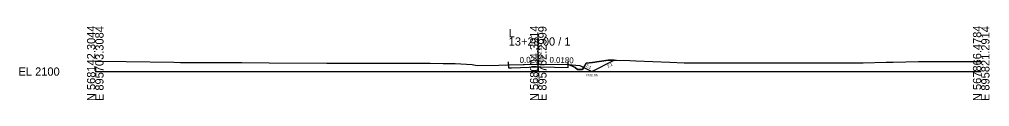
# Model space of a CAD drawing. Extents: x -26 to 1603, y -10 to 13527.
# Drawn here: x -25.7 to 302.8, y 490.3 to 515.5 of the extents above; entities that cross this region are included whole.
import ezdxf

# ---------------------------------------------------------------- set-up
doc = ezdxf.new("R2010")
doc.units = 0
for name, color, linetype in [('Default', 7, 'Continuous'), ('Exist XS Center Line Elevation Label', 7, 'Continuous'), ('Exist XS Ground Line', 7, 'Continuous'), ('Old_Level_61', 7, 'Continuous'), ('Old_Level_63', 7, 'Continuous'), ('Prop XS Ditch Standard Text', 7, 'Continuous'), ('Prop XS Earthwork Shape', 7, 'Continuous'), ('Prop XS EOT Tick Mark', 7, 'Continuous'), ('Prop XS Finish Grade Earthwork', 7, 'Continuous'), ('Prop XS Finish Grade Pavement', 7, 'Continuous'), ('Prop XS Side Slope Text', 7, 'Continuous'), ('Prop XSC Text', 7, 'Continuous')]:
    doc.layers.add(name, color=color, linetype=linetype)

msp = doc.modelspace()

# ---------------------------------------------------------------- linework, layer by layer
at = {"layer": 'Exist XS Ground Line'}
for p, q in [((0, 503.58), (1.9, 503.55)), ((1.9, 503.55), (10.48, 503.42)), ((10.48, 503.42), (26.61, 503.13)), ((26.61, 503.13), (28.82, 503.12)), ((28.82, 503.12), (30.49, 503.09)), ((30.49, 503.09), (44.55, 503.09)), ((44.55, 503.09), (47.96, 503.08)), ((47.96, 503.08), (48.78, 503.04)), ((48.78, 503.04), (49.64, 503.03)), ((49.64, 503.03), (58.91, 502.97)), ((58.91, 502.97), (78.41, 502.89)), ((78.41, 502.89), (84.58, 502.84)), ((84.58, 502.84), (95.98, 502.82)), ((95.98, 502.82), (100.76, 502.79)), ((100.76, 502.79), (109.26, 502.9)), ((109.26, 502.9), (113.38, 502.79)), ((113.38, 502.79), (117.78, 502.75)), ((117.78, 502.75), (120.43, 502.7)), ((120.43, 502.7), (121.91, 502.68)), ((121.91, 502.68), (127.65, 502.34)), ((165.71, 501.83), (166.24, 502.8)), ((166.24, 502.8), (168.33, 503.07)), ((168.33, 503.07), (173.66, 503.86)), ((173.66, 503.86), (176.48, 503.84)), ((176.48, 503.84), (181.01, 503.74)), ((181.01, 503.74), (183.04, 503.65)), ((183.04, 503.65), (188.8, 503.4)), ((188.8, 503.4), (194.55, 503.13)), ((194.55, 503.13), (199.43, 503.01)), ((199.43, 503.01), (200.39, 502.99)), ((200.39, 502.99), (210.5, 502.92)), ((210.5, 502.92), (216.99, 502.96)), ((216.99, 502.96), (223.29, 502.96)), ((223.29, 502.96), (236.58, 502.97)), ((236.58, 502.97), (249.73, 502.91)), ((249.73, 502.91), (253.16, 502.95)), ((253.16, 502.95), (256.79, 502.95)), ((256.79, 502.95), (259.99, 503.01)), ((259.99, 503.01), (267.82, 503.16)), ((267.82, 503.16), (268.75, 503.19)), ((268.75, 503.19), (270.19, 503.21)), ((270.19, 503.21), (278.78, 503.36)), ((278.78, 503.36), (280.93, 503.4)), ((280.93, 503.4), (289.92, 503.42)), ((289.92, 503.42), (296.56, 503.39)), ((296.56, 503.39), (300, 503.41)), ((127.65, 502.34), (129.32, 502.02)), ((129.32, 502.02), (136.66, 502.21)), ((136.66, 502.21), (139.87, 502.26)), ((139.87, 502.26), (150.03, 502.55)), ((150.03, 502.55), (150.49, 502.56)), ((150.49, 502.56), (150.88, 502.56)), ((150.88, 502.56), (160.11, 502.39)), ((160.11, 502.39), (161.38, 501.98)), ((161.38, 501.98), (162.54, 501.38)), ((162.54, 501.38), (163.34, 500.73)), ((163.34, 500.73), (163.9, 500.73)), ((163.9, 500.73), (164.97, 500.73)), ((164.97, 500.73), (165.71, 501.83))]:
    msp.add_line(p, q, dxfattribs=at)
at = {"layer": 'Old_Level_61'}
for p, q in [((139.9, 502.26), (139.9, 501.26)), ((139.9, 501.26), (140.9, 501.29)), ((140.9, 501.29), (150.03, 501.55)), ((150.03, 501.55), (150.49, 501.56)), ((150.49, 501.56), (150.88, 501.56)), ((150.88, 501.56), (160.11, 501.39)), ((160.11, 501.39), (160.13, 501.38)), ((160.13, 501.38), (160.13, 502.38))]:
    msp.add_line(p, q, dxfattribs=at)
at = {"layer": 'Old_Level_63'}
for p, q in [((150, 500), (150, 511.59)), ((0, 500), (150, 500)), ((150, 500), (300, 500))]:
    msp.add_line(p, q, dxfattribs=at)
at = {"layer": 'Prop XS Earthwork Shape'}
for points in [[(168.15, 500.05), (175.75, 503.85), (173.66, 503.86), (168.33, 503.07), (166.24, 502.8), (165.71, 501.83), (165.43, 501.41)], [(168.15, 500.05), (175.75, 503.85), (173.66, 503.86), (168.33, 503.07), (166.24, 502.8), (165.71, 501.83), (165.43, 501.41)], [(160.11, 502.39), (164.11, 502.07), (165.43, 501.41), (164.97, 500.73), (163.9, 500.73), (163.34, 500.73), (162.54, 501.38), (161.38, 501.98)], [(160.11, 502.39), (164.11, 502.07), (165.43, 501.41), (164.97, 500.73), (163.9, 500.73), (163.34, 500.73), (162.54, 501.38), (161.38, 501.98)]]:
    msp.add_lwpolyline(points, close=True, dxfattribs=at)
at = {"layer": 'Prop XS EOT Tick Mark'}
for p, q in [((139.9, 502.26), (139.9, 503.26)), ((160.11, 502.39), (160.11, 503.39))]:
    msp.add_line(p, q, dxfattribs=at)
at = {"layer": 'Prop XS Finish Grade Earthwork'}
for p, q in [((168.15, 500.05), (175.75, 503.85)), ((160.11, 502.39), (164.11, 502.07)), ((164.11, 502.07), (168.15, 500.05))]:
    msp.add_line(p, q, dxfattribs=at)
at = {"layer": 'Prop XS Finish Grade Pavement'}
for p, q in [((139.9, 502.26), (150.5, 502.56)), ((150.5, 502.56), (160.11, 502.39))]:
    msp.add_line(p, q, dxfattribs=at)

# ---------------------------------------------------------------- texts
at = {"layer": 'Default'}
for s, rotation, p in [('0.0280', 1.1458, (143.71, 502.92)), ('0.0180', 358.8542, (153.79, 502.97))]:
    msp.add_text(s, height=2, rotation=rotation, dxfattribs=at).set_placement(p)
at = {"layer": 'Exist XS Center Line Elevation Label'}
msp.add_text('2102.55', height=1, rotation=90, dxfattribs=at).set_placement((150.5, 495.02))
at = {"layer": 'Old_Level_63'}
for s, p in [('N 568142.3044', (0, 490)), ('E 895703.3084', (2.8, 490)), ('N 568004.3914', (150, 490)), ('E 895762.2999', (152.8, 490)), ('N 567866.4784', (300, 490)), ('E 895821.2914', (302.8, 490))]:
    msp.add_text(s, height=2.8, rotation=90, dxfattribs=at).set_placement(p)
for s, p in [('L', (140, 511.59)), ('13+28.00 / 1', (140, 508.79)), ('EL 2100', (-26, 498.6))]:
    msp.add_text(s, height=2.8, dxfattribs=at).set_placement(p)
at = {"layer": 'Prop XS Ditch Standard Text'}
msp.add_text('2100.05', height=0.8, dxfattribs=at).set_placement((166.08, 498.34))
at = {"layer": 'Prop XS Side Slope Text'}
for rotation, p in [(26.5431, (173.59, 501.23)), (332.8476, (165.95, 501.71))]:
    msp.add_text('2:1', height=1, rotation=rotation, dxfattribs=at).set_placement(p)
at = {"layer": 'Prop XSC Text'}
msp.add_text(' 2102.55', height=1.2, rotation=90, dxfattribs=at).set_placement((151.2, 502.55))

doc.saveas('drawing.dxf')
